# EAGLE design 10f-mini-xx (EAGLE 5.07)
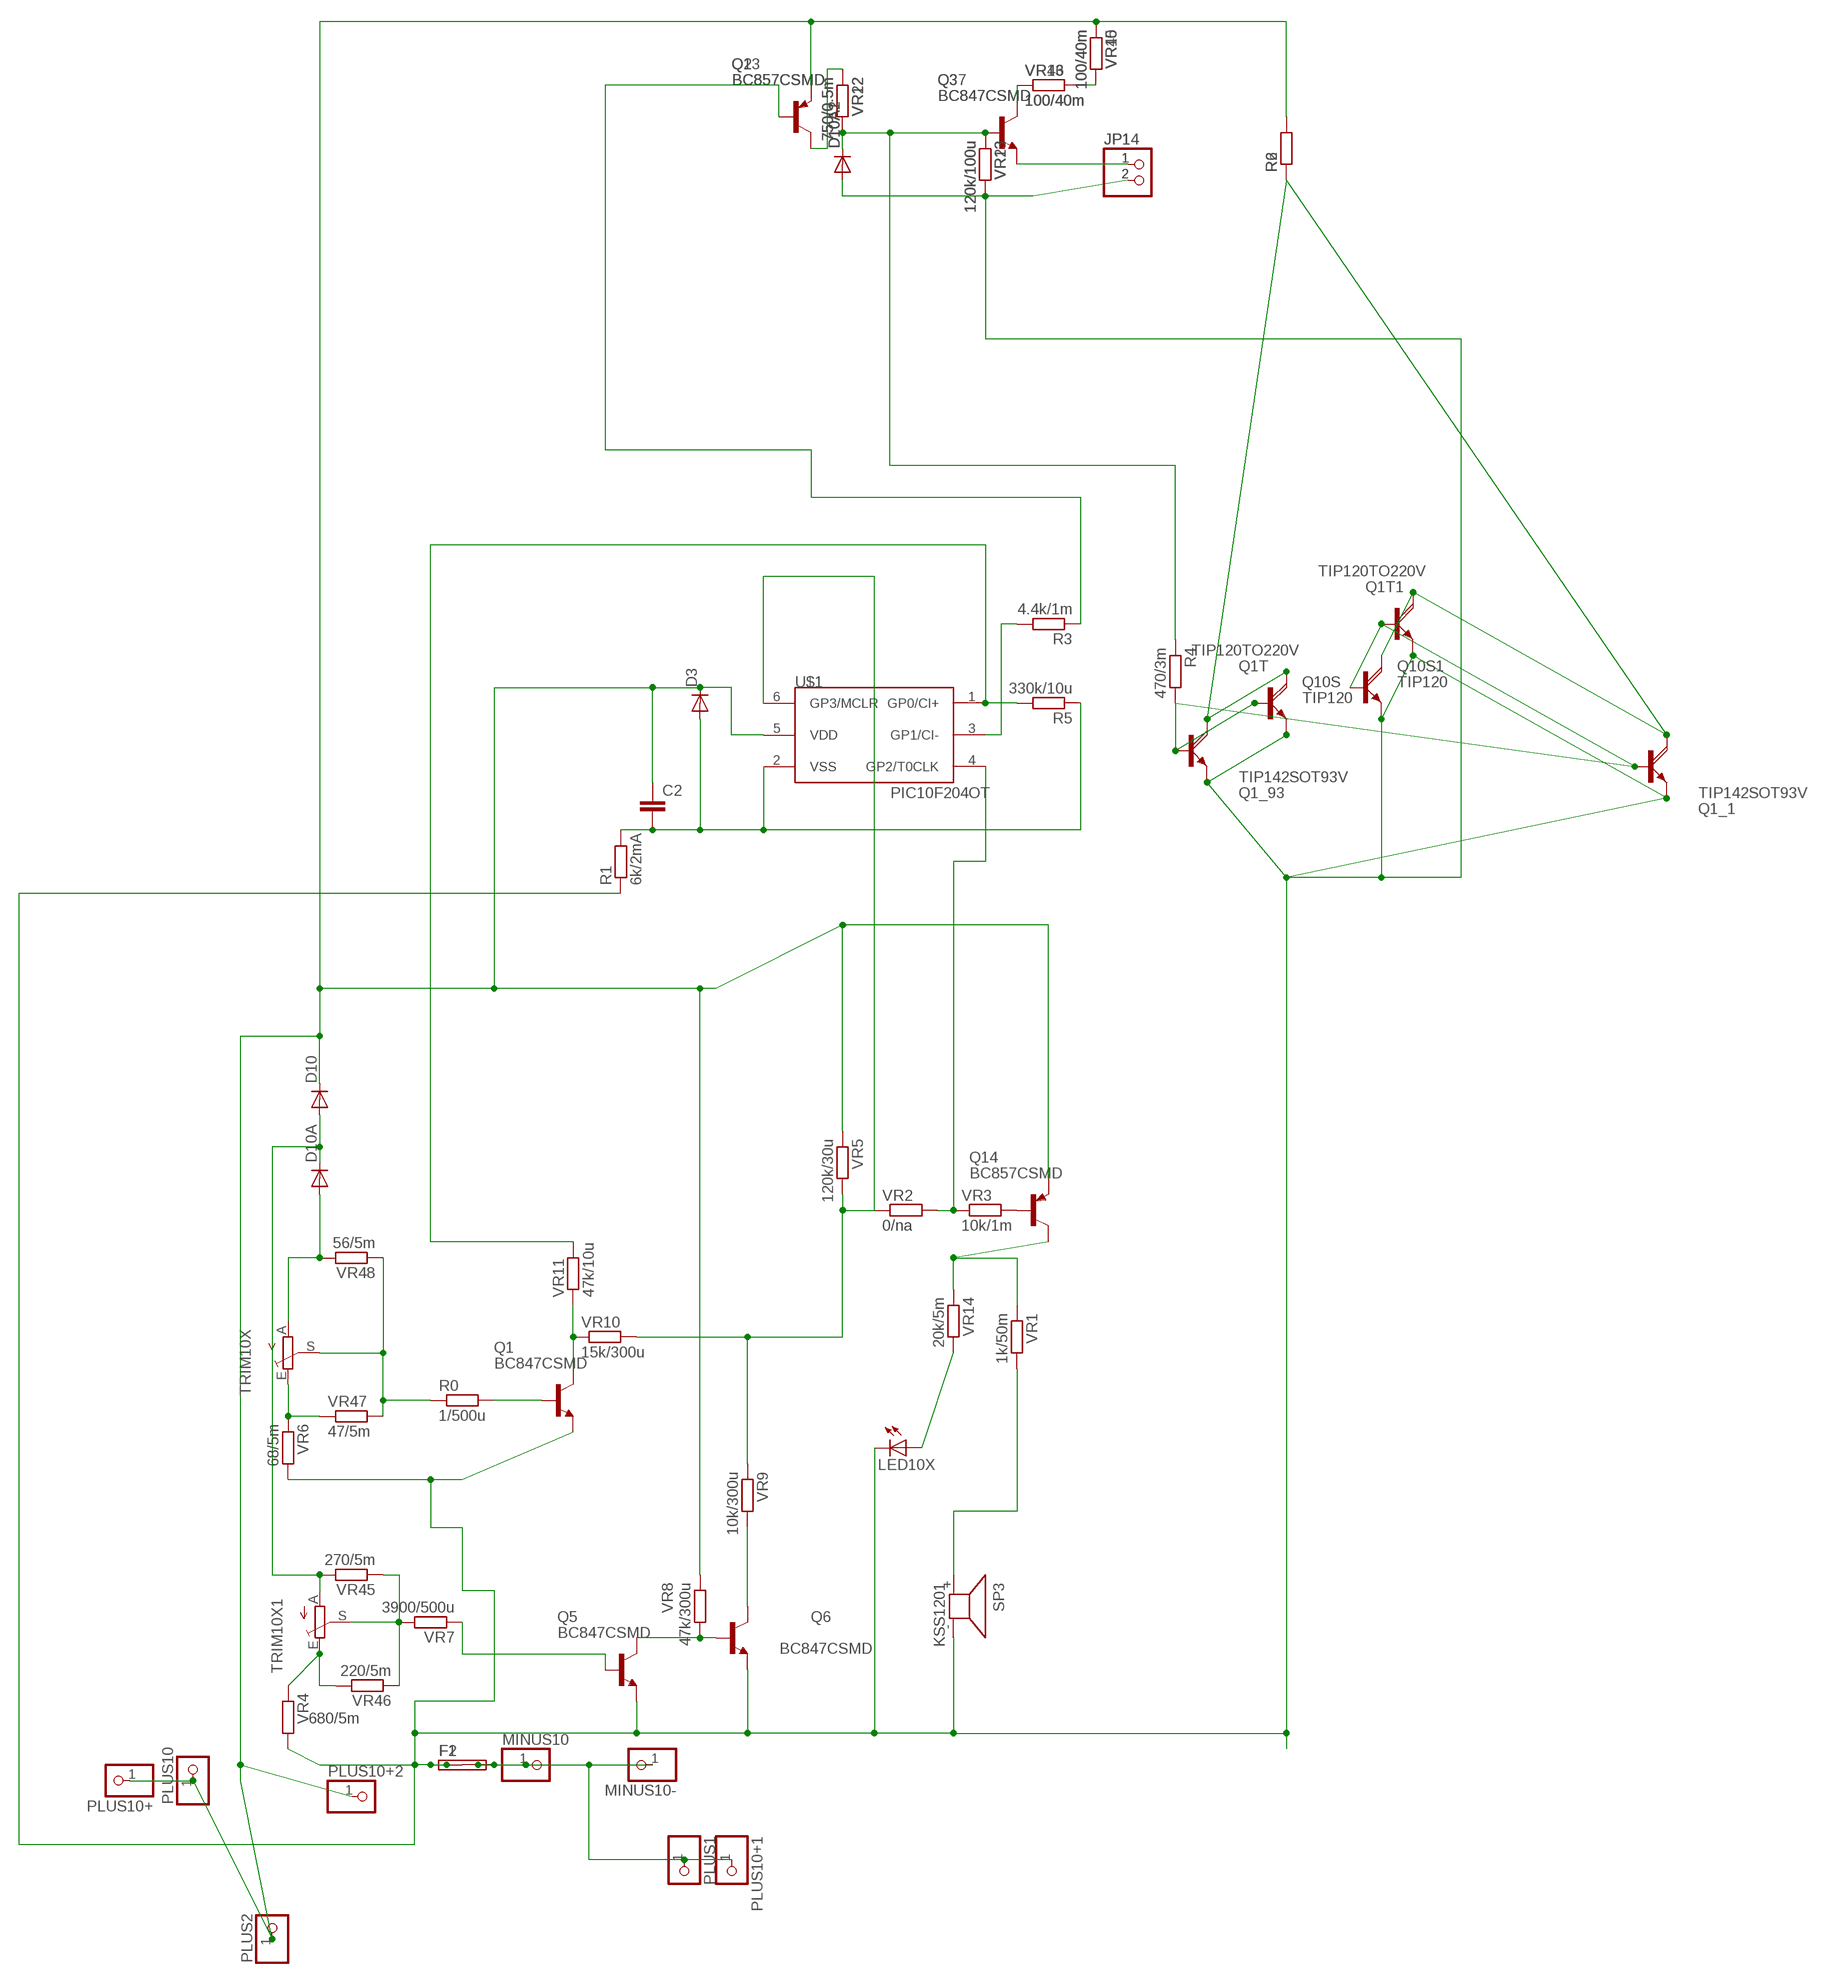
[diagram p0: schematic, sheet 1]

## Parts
C2  C-EUC0805  [C0805]
D3  DIODE-MINIMELF  [MINIMELF]
D10  DIODE-MINIMELF  [MINIMELF]
D10A  DIODE-MINIMELF  [MINIMELF]
D10A1  DIODE-MINIMELF  [MINIMELF]
D10A2  DIODE-MINIMELF  [MINIMELF]
F1  SHK20L  [SHK20L]
F2  SHK20L  [SHK20L]
JP1  PINHD-1X2STR  [1X02]
JP14  PINHD-1X2STR  [1X02]
LED10X  LEDCHIPLED_1206  [CHIPLED_1206]
MINUS10  PINHD-1X14.5MM  [1X4MM5]
MINUS10-  PINHD-1X11X0.4  [1X01]
PLUS1  PINHD-1X14.5MM  [1X4MM5]
PLUS2  PINHD-1X14.5MM  [1X4MM5]
PLUS10  PINHD-1X14.5MM  [1X4MM5]
PLUS10+  PINHD-1X11X0.4  [1X01]
PLUS10+1  PINHD-1X11X0.4  [1X01]
PLUS10+2  PINHD-1X11X0.4  [1X01]
Q1  BC847CSMD  [SOT23]
Q1_1  TIP142SOT93V  [SOT93V]
Q1_93  TIP142SOT93V  [SOT93V]
Q1T  TIP120TO220V  [TO220AV]
Q1T1  TIP120TO220V  [TO220AV]
Q2  BC857CSMD  [SOT23-BEC]
Q3  BC847CSMD  [SOT23]
Q5  BC847CSMD  [SOT23]
Q6  BC847CSMD  [SOT23]
Q10S  TIP120  TIP120DPAK  [D-PAK_TO252AA]
Q10S1  TIP120  TIP120DPAK  [D-PAK_TO252AA]
Q13  BC857CSMD  [SOT23-BEC]
Q14  BC857CSMD  [SOT23-BEC]
Q37  BC847CSMD  [SOT23]
R0  1/500u  R-EU_R1206  [R1206]
R1  6k/2mA  R-EU_R0805  [R0805]
R2  R-EU_CERAM50  [CERAM50]
R3  4.4k/1m  R-EU_R0805  [R0805]
R4  470/3m  R-EU_R0805  [R0805]
R5  330k/10u  R-EU_R0805  [R0805]
R6  R-EU_CERAM70  [CERAM70]
SP3  KSS1201  KSS12017MM  [KSS1202]
TRIM10X  TRIM_EU-S64W  [S64W]
TRIM10X1  TRIM_EU-S64W  [S64W]
U$1  PIC10F204OT  [SOT23-6]
VR1  1k/50m  R-EU_R0805  [R0805]
VR2  0/na  R-EU_R0805  [R0805]
VR3  10k/1m  R-EU_R1206  [R1206]
VR4  680/5m  R-EU_R1206  [R1206]
VR5  120k/30u  R-EU_R0805  [R0805]
VR6  68/5m  R-EU_R1206  [R1206]
VR7  3900/500u  R-EU_M1206  [M1206]
VR8  47k/300u  R-EU_R1206  [R1206]
VR9  10k/300u  R-EU_R0805  [R0805]
VR10  15k/300u  R-EU_R1206  [R1206]
VR11  47k/10u  R-EU_R0805  [R0805]
VR12  750/0.5m  R-EU_R0805  [R0805]
VR13  120k/100u  R-EU_R0805  [R0805]
VR14  20k/5m  R-EU_R0805  [R0805]
VR15  100/40m  R-EU_R1206  [R1206]
VR16  100/40m  R-EU_R1206  [R1206]
VR22  750/0.5m  R-EU_R0805  [R0805]
VR23  120k/100u  R-EU_R0805  [R0805]
VR40  100/40m  R-EU_R1206  [R1206]
VR43  100/40m  R-EU_R1206  [R1206]
VR45  270/5m  R-EU_R0805  [R0805]
VR46  220/5m  R-EU_R1206  [R1206]
VR47  47/5m  R-EU_R0805  [R0805]
VR48  56/5m  R-EU_R0805  [R0805]

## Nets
B: R0.1 TRIM10X.S VR47.2 VR48.1
BUZZ+: SP3.+ VR1.2
FPLUS1: Q2.E R6.2 VR15.1
GP3: U$1.4(GP2/T0CLK) VR2.2 VR3.1
INPLUS: C2.1 D3.C D10.C PLUS2.1 PLUS10+2.1 PLUS10+.1 PLUS10.1 Q13.E Q14.E R2.2 U$1.5(VDD) VR5.1 VR8.1 VR40.1
N$1: R3.2 U$1.3(GP1/CI-)
N$2: Q1.3(C) VR10.1 VR11.1
N$3: Q5.3(C) Q6.1(B) VR8.2
N$4: LED10X.A VR14.2
N$5: Q6.3(C) VR9.2
N$6: U$1.6(GP3/MCLR) VR2.1 VR5.2 VR9.1 VR10.2
N$7: Q1.1(B) R0.2
N$8: Q14.C VR1.1 VR14.1
N$10: Q14.B VR3.2
N$12: Q1_1.B Q1T1.B Q10S1.1(B)
N$13: JP1.1 Q3.2(E)
N$14: D10A.A TRIM10X.A VR48.2
N$15: Q2.B
N$16: Q2.C VR12.1
N$17: D10.A D10A.C TRIM10X1.A VR45.2
N$18: VR15.2 VR16.2
N$19: Q3.3(C) VR16.1
N$20: D10A2.C Q3.1(B) VR12.2 VR13.1
N$22: TRIM10X1.S VR7.2 VR45.1 VR46.1
N$23: Q13.B R3.1
N$24: TRIM10X1.E VR4.1 VR46.2
N$25: Q1_93.B Q1T.B Q10S.1(B) R4.2
N$26: F1.2A F1.2B F2.2A F2.2B MINUS10-.1 MINUS10.1 PLUS1.1 PLUS10+1.1
N$128: TRIM10X.E VR6.1 VR47.1
N$136: JP14.1 Q37.2(E)
N$138: R5.2 U$1.1(GP0/CI+) VR11.2
N$159: Q13.C VR22.1
N$163: VR40.2 VR43.2
N$164: Q37.3(C) VR43.1
N$168: Q5.1(B) VR7.1
N$179: D10A1.C Q37.1(B) R4.1 VR22.2 VR23.1
Q10C: Q1_93.C Q1T.C Q10S.4(C) R2.1
Q10C1: Q1_1.C Q1T1.C Q10S1.4(C) R6.1
VSS: D10A1.A D10A2.A F1.1A F1.1B F2.1A F2.1B JP1.2 JP14.2 LED10X.C Q1.2(E) Q1_1.E Q1_93.E Q1T1.E Q1T.E Q5.2(E) Q6.2(E) Q10S1.3(E) Q10S.3(E) R1.1 SP3.- VR4.2 VR6.2 VR13.2 VR23.2
VSS1: C2.2 D3.A R1.2 R5.1 U$1.2(VSS)

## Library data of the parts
C2 = rcl:C-EU: CAPACITOR, European symbol
D3 D10 D10A D10A1 D10A2 = diode:DIODE-: DIODE
F1 F2 = fuse:SHK20L: FUSE HOLDER 5 x 20 mm, SH contact, SHH1 Schukat, E1073 Buerklin
JP1 JP14 = pinhead:PINHD-1X2: PIN HEADER
LED10X = led:LED: LED
MINUS10 MINUS10- PLUS1 PLUS2 PLUS10 PLUS10+ PLUS10+1 PLUS10+2 = pinhead:PINHD-1X1: PIN HEADER
Q1 Q3 Q5 Q6 Q37 = transistor-npn:BC847*: NPN Transistor
Q1_1 Q1_93 = transistor-power:TIP142: NPN DARLINGTON TRANSISTOR
Q1T Q1T1 Q10S Q10S1 = transistor-power:TIP120: NPN DARLINGTON TRANSISTOR
Q2 Q13 Q14 = transistor-pnp:BC857*: PNP Transistror
R0 R1 R3-R5 VR1-VR16 VR22 VR23 VR40 VR43 VR45-VR48 = rcl-2:R-EU_: RESISTOR, European symbol
R2 R6 = rcl:R-EU_: RESISTOR, European symbol
SP3 = buzzer:KSS1201: SPEAKER
TRIM10X TRIM10X1 = pot:TRIM_EU-: POTENTIOMETER
U$1 = microchip-3:PIC10F2*: uPC nW 0,25/0,5k Program Flash memory Comparator

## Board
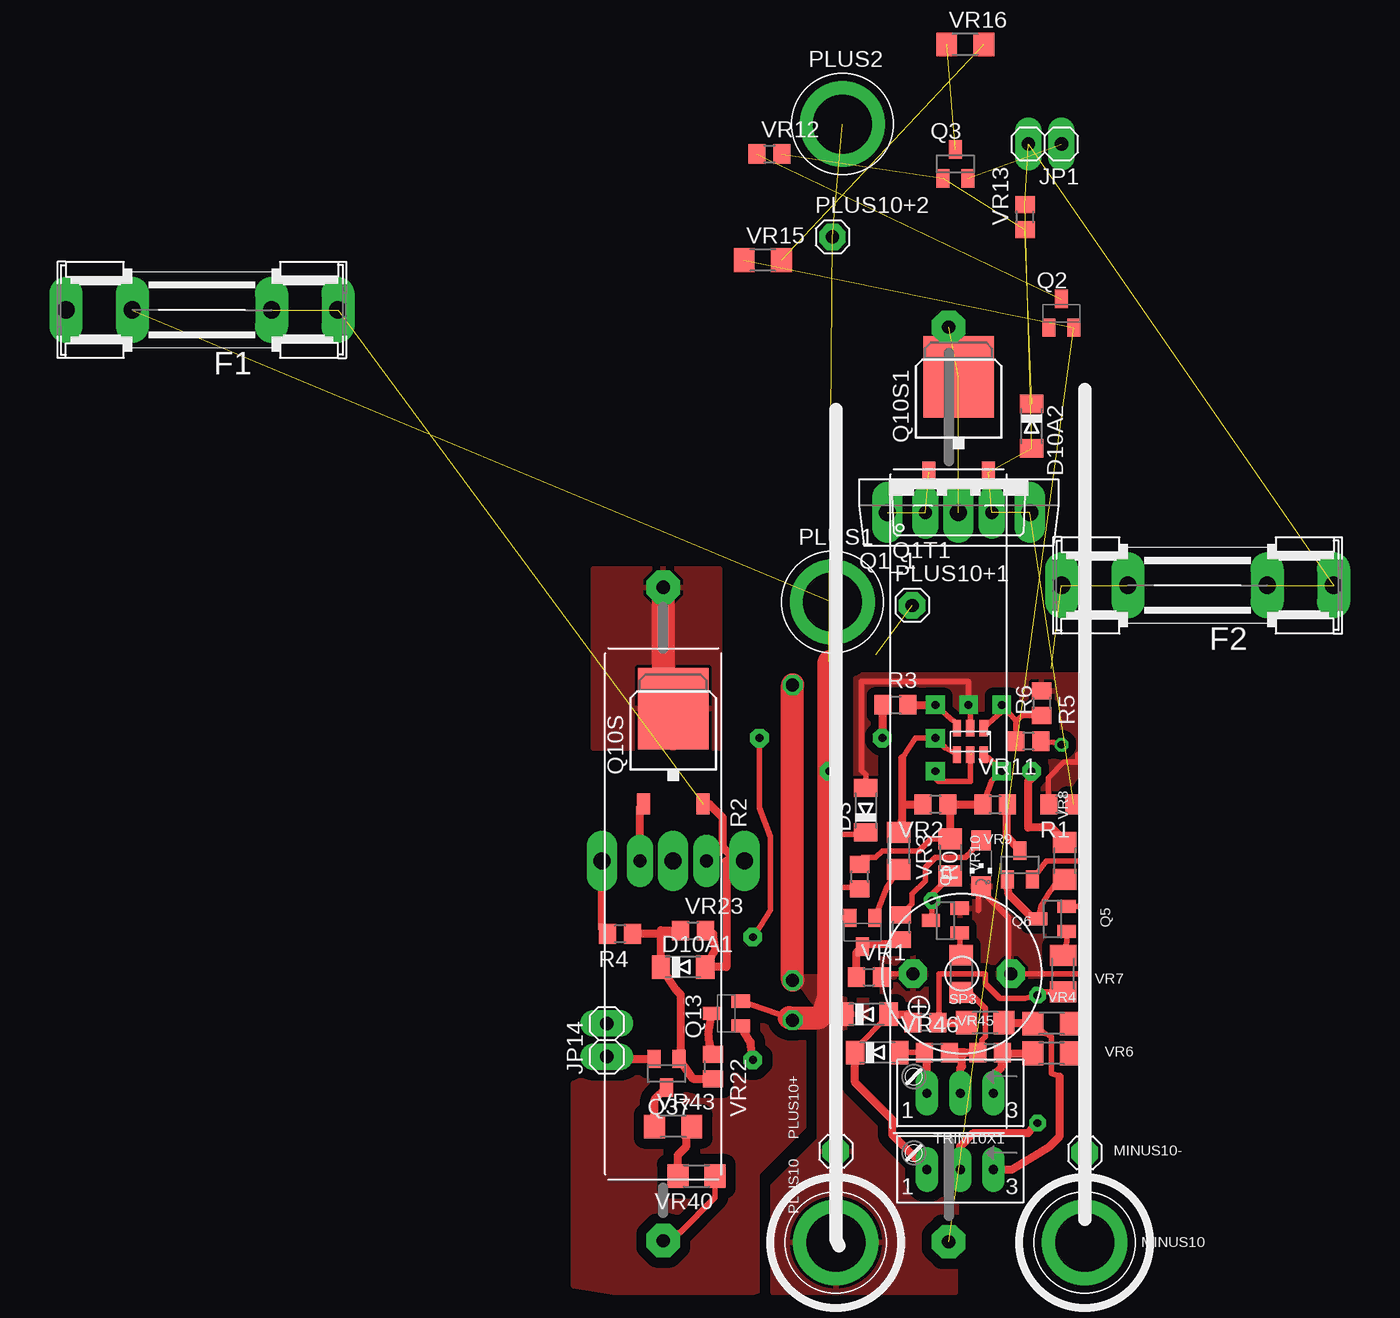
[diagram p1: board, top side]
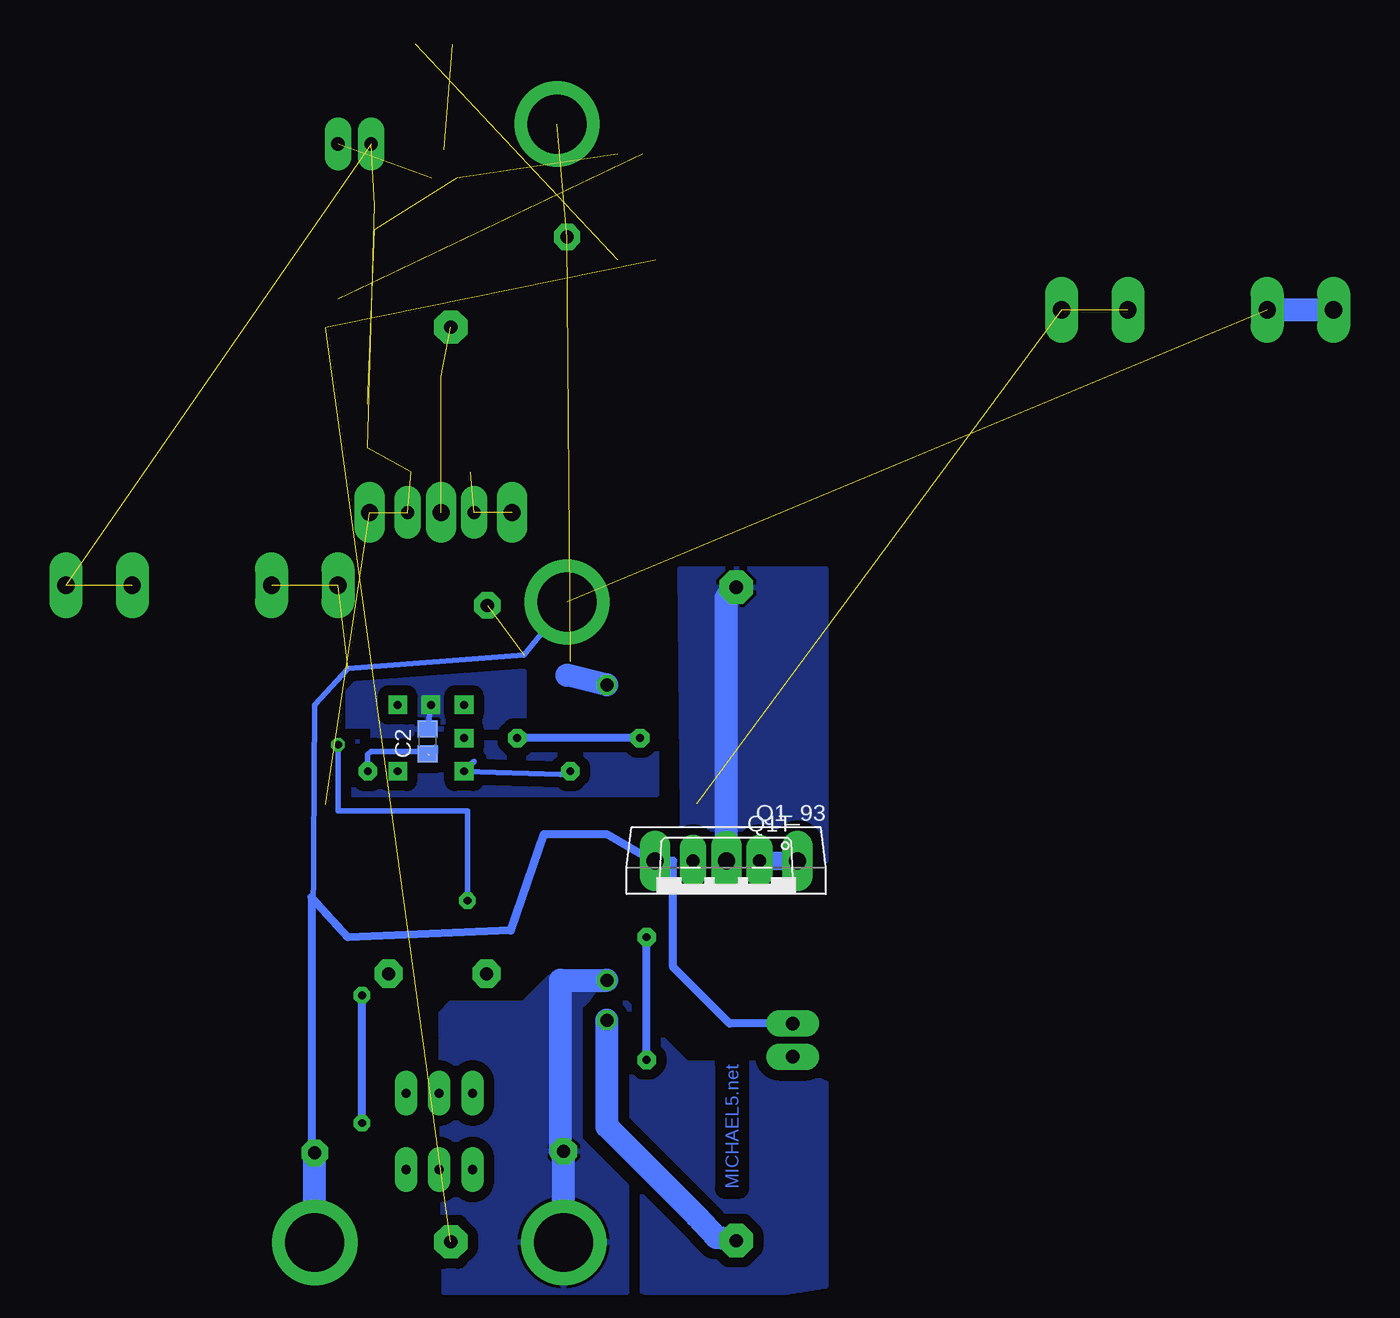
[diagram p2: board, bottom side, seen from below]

No outline drawn. Coordinates in mm, seen from the top.
Copper layers (1*16): Top 0.035mm / dielectric 1.5mm / Bottom 0.035mm
Design rules "default *": minimum track width 8mil, minimum drill 4mil, track to track 8mil, track to pad 8mil, pad to pad 8mil, via to via 8mil, smd to smd 8mil, copper to edge 40mil, drill to drill 8mil, minimum pad ring 20mil, minimum via ring 8mil, stop-mask expansion 4mil, vias tented up to drill 0mil, thermal gap 10mil

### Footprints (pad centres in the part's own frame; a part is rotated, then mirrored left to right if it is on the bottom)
C0805 = smd 1.3 x 1.5: 1 -0.95,0; 2 0.95,0
MINIMELF = smd 1.4 x 1.8: A 1.7,0; C -1.7,0
SHK20L = drill 1.321 pad 2.54 long: 1A -10.414,0; 1B -5.334,0; 2A 10.414,0; 2B 5.334,0
1X02 = drill 1.016 pad 1.676 long: 1 -1.27,0; 2 1.27,0
CHIPLED_1206 = smd 1.5 x 1.5: A 0,-1.75; C 0,1.75
1X4MM5 = drill 4.5 pad 6.35 round: 1 0,0
1X01 = drill 1 pad 1.676 octagon: 1 0,0
SOT23 = smd 1 x 1.4: 1 -0.95,-1.1; 2 0.95,-1.1; 3 0,1.1
SOT93V = drill 1.3 pad 1.676 long: B -5.461,-2.54; C 0,-2.54; E 5.461,-2.54
TO220AV = drill 1 pad 1.27 long: B -2.54,-2.54; C 0,-2.54; E 2.54,-2.54
SOT23-BEC = smd 1 x 1.4: B -0.95,-1.1; C 0,1.1; E 0.95,-1.1
D-PAK_TO252AA = smd 1 x 1.6: 1 -2.28,-4.8; 3 2.28,-4.8 | smd 5.4 x 6.2: 4 0,2.5
R1206 = smd 1.6 x 1.803: 1 -1.422,0; 2 1.422,0
R0805 = smd 1.3 x 1.5: 1 -0.95,0; 2 0.95,0
CERAM50 = drill 1 pad 2.54 octagon: 1 -25,0; 2 25,0
CERAM70 = drill 1 pad 2.54 octagon: 1 -35,0; 2 35,0
KSS1202 = drill 1 pad 2.159 octagon: + 3.75,0; - -3.75,0
S64W = drill 0.7 long: A 2.54,1.27; E -2.54,1.27; S 0,1.27
SOT23-6 = smd 0.635 x 1.27: 1 -1.016,-1.016; 2 0,-1.016; 3 1.016,-1.016; 4 1.016,1.016; 5 0,1.016; 6 -1.016,1.016
M1206 = smd 1.6 x 2: 1 -1.4,0; 2 1.4,0

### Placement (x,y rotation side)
C2  81.53,47.24 90 bottom
D3  73.41,41.97 90 top
D10  73.47,26.35 0 top
D10A  74.3,23.43 0 top
D10A1  59.44,29.97 0 top
D10A2  86.11,71.37 270 top
F1  22.61,80.26 180 top
F2  98.81,59.18 180 top
JP1  87.12,92.96 180 top
JP14  53.59,24.38 90 top
LED10X  82.23,37.91 180 top
MINUS10  90.17,8.89 0 top
MINUS10-  90.17,15.75 0 top
PLUS1  70.87,57.91 0 top
PLUS2  71.63,94.49 0 top
PLUS10  71.12,8.89 0 top
PLUS10+  71.12,15.88 0 top
PLUS10+1  76.96,57.66 0 top
PLUS10+2  70.87,85.85 0 top
Q1  79.5,33.53 90 top
Q1_1  80.52,67.31 0 top
Q1_93  58.67,35.56 180 bottom
Q1T  58.67,35.56 180 bottom
Q1T1  80.52,67.31 0 top
Q2  88.39,80.01 0 top
Q3  80.26,91.44 0 top
Q5  87.69,33.66 90 top
Q6  85.22,37.78 0 top
Q10S  58.67,47.24 0 top
Q10S1  80.52,72.64 0 top
Q13  62.74,26.42 90 top
Q14  73.15,32.64 180 top
Q37  58.17,21.84 180 top
R0  80.71,29.46 90 top
R1  88.39,42.42 180 top
R2  57.91,34.04 270 top
R3  75.69,50.04 0 top
R4  54.61,32.51 180 top
R5  86.87,50.16 270 top
R6  79.76,43.94 270 top
SP3  80.77,29.46 180 top
TRIM10X  80.64,21.59 180 top
TRIM10X1  80.64,15.75 180 top
U$1  81.41,47.24 180 top
VR1  73.66,29.21 0 top
VR2  78.74,42.42 180 top
VR3  75.95,38.86 270 top
VR4  87.63,25.65 0 top
VR5  72.96,36.89 90 top
VR6  87.63,23.37 0 top
VR7  88.52,29.46 270 top
VR8  88.65,38.1 270 top
VR9  83.31,42.42 0 top
VR10  79.88,38.35 90 top
VR11  85.85,47.24 180 top
VR12  66.04,92.2 0 top
VR13  85.6,87.38 90 top
VR14  76.14,33.02 90 top
VR15  65.53,84.07 0 top
VR16  81.03,100.58 0 top
VR22  61.72,22.35 270 top
VR23  60.2,32.77 0 top
VR40  60.45,13.97 180 top
VR43  58.67,17.78 0 top
VR45  77.98,25.72 180 top
VR46  82.55,25.72 0 top
VR47  82.93,23.43 180 top
VR48  78.87,23.43 180 top

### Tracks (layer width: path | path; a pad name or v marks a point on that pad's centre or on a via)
B
  Top 0.406: VR47.2 82.3,23.75 82.3,24.38 82.55,24.64 82.55,26.8 81.18,28.17 R0.1 | 80.64,22.23 80.77,22.35
  Top 0.61: 81.03,23.43 VR48.1 | 81.03,23.43 VR47.2 | TRIM10X.S 80.64,22.23 | 80.77,22.35 80.77,23.18 81.03,23.43
BUZZ+
  Top 0.406: SP3.+ 74.86,29.46 VR1.2
  pour Top (isolate 0.61): 75.44,31.24 78.99,31.24 79.5,30.73 79.5,27.18 79.25,26.92 75.44,26.92 74.68,27.69 74.68,30.73
FPLUS
  pour Bottom (isolate 0.813): 64.01,46.99 87.88,47.24 87.88,43.18 64.01,43.18
  pour Bottom (isolate 0.813, rank 2): 64.77,5.08 54.1,5.08 51.05,5.59 51.05,21.08 53.59,22.35 53.85,22.61 61.72,22.61 66.29,27.18 68.58,27.18 69.6,26.16 69.6,16.76 65.79,12.95 65.79,5.33
  pour Top (isolate 0.813, rank 2): 64.77,5.08 54.1,5.08 51.05,5.59 51.05,21.08 53.59,22.35 53.85,22.61 61.72,22.61 66.29,27.18 68.58,27.18 69.6,26.16 69.6,16.76 65.79,12.95 65.79,5.33
FPLUS1  (2 unrouted)
GP3  (via drill 0.6 pad 1.42)
  Top 0.406: U$1.4 79.5,46.74 v78.74,47.5 77.22,47.5 76.2,45.97
  Top 0.61: 76.2,42.42 76.2,45.97 | 76.2,42.42 VR2.2 | 76.2,42.42 76.2,41.24 VR3.1
INPLUS  (via drill 0.6 pad 1.42, 1 pad 1.42)  (3 unrouted)
  Top 0.406: VR8.1 88.14,40.13 | U$1.5 81.41,44.2 78.99,44.2 78.74,44.45 v78.74,44.96 | Q13.E 67.56,26.1 67.5,26.1 v67.82,25.91 | VR40.1 61.87,12.34 59.18,9.65 58.53,9.65 R2.2 | Q14.E 71.14,33.78 70.61,34.29 | VR5.1 72.83,36.07 70.61,36.07 | D3.C 73.26,40.13 70.61,40.13 | D10.C 70.67,26.35 70.26,26.76
  Top 0.61: 88.14,40.13 87.63,40.64 85.85,40.64 85.85,44.2 86.11,44.45 v86.11,44.96
  Top 1.422: 69.6,26.1 70.26,26.76
  Top 1.676: 70.26,26.76 70.61,27.87
  Top 1.778: v67.82,28.96 v67.82,51.56 | 67.56,26.1 69.6,26.1 69.85,26.1 | 70.61,53.34 v70.61,44.96 70.61,40.13 70.61,36.07 70.61,34.29 70.61,27.87
  Bottom 0.406: C2.1 80.91,46.8 80.91,46.4 81.03,46.4 81.03,46.48 85.85,46.48 86.11,46.23 v86.11,44.96 | 77.98,45.72 v78.74,44.96 71.37,44.7 v70.61,44.96
  Bottom 1.778: PLUS10.1 PLUS10+.1 71.37,15.88 71.37,28.96 v67.82,28.96 | v67.82,51.56 70.87,52.32 | R2.2 59.44,9.29 60.96,10.92 67.82,17.78 v67.82,25.91
  pour Bottom (isolate 0.813): 68.07,29.21 72.14,29.21 74.17,27.18 79.76,27.18 80.52,26.42 80.26,5.08 66.29,5.08 66.29,13.21 69.85,16.76 69.85,26.92 69.34,27.43
  pour Top (isolate 0.813): 68.07,29.21 72.14,29.21 74.17,27.18 79.76,27.18 80.52,26.42 80.26,5.08 66.29,5.08 66.29,13.21 69.85,16.76 69.85,26.92 69.34,27.43
N$1
  Top 0.406: 78.74,50.04 79.95,48.96 80.33,48.7 U$1.3
  Top 0.61: R3.2 78.74,50.04
N$2  (via drill 0.6 pad 1.02, 0.6 pad 1.27)
  Top 0.406: VR11.1 87.82,47.18 v88.39,46.99 | 79.88,36.45 VR10.1 78.49,35.53 v78.49,35.05 78.49,33.61 Q1.3
  Bottom 0.406: v78.49,35.05 78.49,41.91 88.39,41.91 v88.39,46.99
N$3
  Top 0.406: VR8.2 88.49,37.19 87.38,35.56 86.87,34.69 Q5.3
  Top 0.61: Q6.1 84.33,35.56 86.11,33.78 86.47,33.78 Q5.3
N$4
  Top 0.406: VR14.2 76.39,34.23 76.96,34.8 76.96,35.56 77.98,36.58 77.98,37.59 78.74,38.35 81.03,38.35 81.28,38.61 81.79,39.22 LED10X.A
N$5
  Top 0.406: 84.58,42.23 VR9.2
  Top 0.61: Q6.3 84.2,40.01 84.2,42.16 84.58,42.23
N$6
  Top 0.406: VR9.1 83.06,44.26 83.82,44.96 82.8,45.97 U$1.6 | VR10.2 78.38,39.78 77.47,38.86 74.68,38.86 74.17,38.35 73.15,38.36 VR5.2 | 79.88,42.23 VR2.1
  Top 0.61: VR2.1 VR9.1 | VR10.2 79.88,42.23
N$7
  Top 0.406: Q1.1 80.6,30.99 R0.2
N$8
  Top 0.406: 75.95,31.75 76.33,32.13 VR14.1 | 73.55,31.75 Q14.C 72.71,31.1
  Top 0.61: 73.55,31.75 75.95,31.75 | VR1.1 72.71,31.1
N$9  (via drill 0.6 pad 1.42)
  other vias: 83.82,44.96
N$10
  Top 0.406: Q14.B 75.04,36.09 VR3.2
N$11  (via drill 0.6 pad 1.42)
  other vias: 83.82,50.04
N$12  (2 unrouted)
N$13  (1 unrouted)
N$14
  Top 0.406: 78.11,23.37 VR48.2 D10A.A
  Top 0.61: TRIM10X.A 78.11,23.37
N$16  (1 unrouted)
N$17
  Top 0.406: 76.58,26.35 VR45.2 | D10A.C 72.59,23.65 D10.A
  Top 0.61: D10.A 76.58,26.35 | D10A.C 72.59,21.13 75.44,18.29 75.44,17.14 TRIM10X1.A
N$18  (1 unrouted)
N$19  (1 unrouted)
N$20  (3 unrouted)
N$22  (via drill 0.6 pad 1.27)
  Top 0.406: VR45.1 78.99,25.72 78.99,29.46 82.55,29.46 82.55,28.7 83.69,27.56 85.6,27.56 v86.55,27.81 86.93,28.06 VR7.2
  Top 0.61: 78.99,25.72 VR46.1 | TRIM10X1.S 80.64,16.26 81.66,17.27 85.85,17.27 v86.55,18.03
  Bottom 0.61: v86.55,18.03 v86.55,27.81
N$23  (via drill 0.6 pad 1.42)
  Top 0.406: v64.77,32.26 65.79,33.78 66.1,34.35 66.1,39.94 65.28,42.16 v65.28,47.5
  Top 0.61: R3.1 74.74,47.82 v74.68,47.5 | Q13.B 64.6,24.21 v64.77,22.86
  Bottom 0.61: v65.28,47.5 v74.68,47.5 | v64.77,22.86 v64.77,32.26
N$24
  Top 0.406: 88.27,21.59 87.63,21.84 87.63,24.64 87.12,24.89 86.46,25.4 VR4.1 | 84.03,25.65 VR46.2
  Top 0.61: TRIM10X1.E 84.58,14.48 87.5,16.26 88.27,17.02 88.27,21.59 | VR4.1 84.03,25.65
N$25
  Top 0.61: Q1_93.B 53.21,32.96 R4.2 | Q1T.B 56.13,42.18 Q10S.1
  Bottom 1.422: Q1_93.B Q1T.B
N$26  (4 unrouted)
  Bottom 0.406: PLUS1.1 74.17,53.85 87.63,52.83 90.17,50.04 90.42,16 MINUS10-.1
  Bottom 1.778: F1.2A F1.2B | MINUS10.1 MINUS10-.1
N$128
  Top 0.406: 83.82,23.37 VR47.1 83.82,23.37
  Top 0.61: TRIM10X.E 83.19,21.72 83.82,22.35 83.82,23.37 | 83.82,23.37 VR6.1
N$136
  Top 0.61: Q37.2 53.76,22.94 JP14.1
N$138
  Top 0.406: VR11.2 84.89,48.82 | 84.89,48.82 84.14,49.72 83.82,50.04 83.82,49.53 U$1.1 | R5.2 85.39,49.22 84.89,48.82
N$159
  Top 0.61: Q13.C 61.38,24.98 61.47,24.13 VR22.1
N$163
  Top 0.61: VR40.2 59.03,15.6 59.69,16.26 59.69,17.37 VR43.2
N$164
  Top 0.61: VR43.1 57.25,19.83 Q37.3
N$168
  Top 0.406: Q5.1 88.79,31.9 VR7.1
N$179
  Top 0.61: R4.1 58.99,32.51 VR23.1 57.72,32.78 D10A1.C 58.93,28.19 59.26,27.86 59.26,23.09 Q37.1 60.18,21.42 VR22.2
Q10C
  Top 1.422: 58.93,49.02 58.93,49.49 Q10S.4
  Top 1.778: R2.1 57.91,50.04 58.93,49.02
  Bottom 1.778: Q1_93.C 58.67,58.27 R2.1
  pour Top (isolate 0.813): 52.58,60.45 62.23,60.45 62.23,46.74 52.58,46.74
  pour Bottom (isolate 0.813): 51.05,60.45 62.23,60.45 61.98,38.1 51.05,38.1
Q10C1  (2 unrouted)
VDF  (via drill 0.6 pad 1.42)
  other vias: 78.74,50.04
VSS  (10 unrouted)
  Top 0.406: 90.17,25.4 90.17,23.37 VR6.2 | VR4.2 89.92,25.65 90.17,25.4 | 90.04,29.84 90.17,29.72 90.17,25.4 | 90.04,29.84 89.92,29.46 SP3.- 84.33,29.66 84.33,33.78 82.23,35.88 LED10X.C 82.04,35.97 82.04,34.29 | Q5.2 89.86,34.6 90.17,34.29 | 90.17,34.29 90.17,29.97 90.04,29.84 | R1.1 89.92,42.42 90.17,42.16 90.17,38.1 | 90.17,34.29 90.17,38.1 | Q6.2 87.23,38.1 90.17,38.1
  Top 0.61: VR23.2 61.72,32.51 61.9,31.32 D10A1.A 62.74,29.97 62.74,38.1 64.26,37.97 Q1_93.E 63.5,38.1 62.48,39.12 | Q1T.E 61.47,38.1 62.48,39.12 | 62.48,39.12 62.48,41.4 61.47,42.42 60.98,42.42 Q10S.3
  Bottom 0.61: 90.42,16 90.42,35.31 87.63,32.26 75.18,32.77 72.64,40.13 67.82,40.13 64.14,37.97 Q1_93.E 62.74,38.1 62.74,29.97 58.42,25.65 JP14.2
  pour Top (isolate 0.61): 81.53,36.83 81.53,34.8 80.52,33.78 80.52,32 84.58,27.94 90.17,27.94 90.42,28.19 90.42,30.73 89.66,31.5 87.12,31.5 87.12,34.29 85.6,35.05
VSS1  (via drill 0.6 pad 1.42)
  Top 0.406: 89.66,46.23 89.66,45.66 88.58,45.66 87.38,44.45 87.38,42.61 | U$1.2 81.41,49.78 v81.28,50.04 81.28,51.82 73.09,51.82 73.09,45.02 73.41,44.7 D3.A | R5.1 87.12,51.24
  Top 0.61: R1.2 87.38,42.61
  Bottom 0.406: v81.28,50.04 C2.2
  pour Bottom (isolate 0.813, rank 2): 74.17,52.58 87.63,52.58 87.63,47.75 74.17,47.5
  pour Top (isolate 0.61): 72.64,44.45 72.64,52.07 73.15,52.32 89.92,52.32 89.92,45.15 88.39,42.93 86.61,42.93 86.61,48.77 87.38,49.53 87.38,50.04 86.87,50.55 83.31,50.55 82.3,49.53 80.26,49.53 80.26,49.78 79.5,50.55 74.68,50.55 74.17,50.04 74.17,44.2

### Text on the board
Bottom: MICHAEL5.net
